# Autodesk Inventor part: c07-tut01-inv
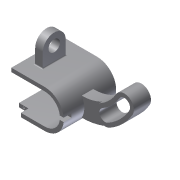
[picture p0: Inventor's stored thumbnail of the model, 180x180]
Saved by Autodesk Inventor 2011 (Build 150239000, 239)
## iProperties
Created: 2010-03
Part Number: c07-tut01-inv
Document SubType Name: Modeling
Designer: CADSoft
Density: 1 g/cm^3
Author: CADSoft
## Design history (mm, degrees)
sketch "Sketch1"
  geometry: 1 further point
sketch "Sketch2"
  geometry: L1 (0, 20)-(35, 20); L2 (35, 20)-(35, 16); L3 (35, 16)-(0, 16); L4 (0, -16)-(35, -16); L5 (35, -16)-(35, -20); L6 (35, -20)-(0, -20); A1 r 20 centre (0, 0) between (0, 20) and (0, -20); A2 r 16 centre (0, 0) between (0, 16) and (0, -16); 1 further point
  constraints: 12 end point, 4 point on circle, 3 equal length, 2 centre point, 1 coincident
  dimensions: "d0" = 20 radius of A1; "d1" = 35 distance of L1.start L1.end; "d2" = 4 distance of L1.end L2.end
extrude "Extrusion1" new body sketch "Sketch2" stored distance "d3" = 55; taper "d4" = 0 deg
sketch "Sketch3"
  geometry: A1 r 45 centre (-17.5, 55) between (-56.409, 32.393) and (-17.32, 10); A2 r 65 centre (-17.5, 55) between (-73.702, 22.345) and (-17.321, -10); A3 r 20 centre (0, 0) between (-17.32, 10) and (-17.321, -10); A4 r 10 centre (-65.055, 27.369) between (-56.409, 32.393) and (-73.702, 22.345); 1 further point
  constraints: 8 point on circle, 4 centre point, 2 coincident, 2 tangent
  dimensions: "d5" = 45 radius of A1; "d6" = 65 radius of A2; "d7" = 17.5 horizontal distance of point (0, 0) A1.centre; "d8" = 55 vertical distance of point (0, 0) A1.centre; "d9" = 60 deg dimension on A1.centre A2.start A2.end; "d10" = 20 radius of A3
extrude "Extrusion2" join sketch "Sketch3" stored distance "d11" = 12; taper "d12" = 0 deg
hole "Hole1" diameter "d52" = 2; stored, may be unused: countersink angle "d56" = 90 deg, drill point angle "d58" = 118 deg; dims "d50" = 5, "d51" = 2, "d53" = 6, "d54" = 4, "d55" = 2, "d57" = 4
body "Solid1"
sketch "Sketch4"
  geometry: A1 r 45 centre (-17.5, 55) between (-56.409, 32.393) and (-39.892, 15.967); A2 r 65 centre (-17.5, 55) between (-73.702, 22.345) and (-49.845, -1.381); A3 r 10 centre (-65.055, 27.369) between (-56.409, 32.393) and (-73.702, 22.345); A4 r 10 centre (-44.868, 7.293) between (-49.845, -1.381) and (-39.892, 15.967); A5 r 10 centre (-65.055, 27.369) between (-56.409, 32.393) and (-73.702, 22.345) reference; A6 r 45 centre (-17.5, 55) between (-56.409, 32.393) and (-17.32, 10) reference; A7 r 65 centre (-17.5, 55) between (-73.702, 22.345) and (-17.321, -10) reference; 1 further point
  constraints: 8 point on circle, 4 centre point, 4 tangent, 3 concentric, 1 coincident
  dimensions: "d30" = 10 radius of A3; "d31" = 30 deg dimension on A1.centre A4.centre A3.centre
extrude "Extrusion3" join sketch "Sketch4" stored distance "d32" = 18; taper "d33" = 0 deg
sketch "Sketch5"
  geometry: A1 r 10 centre (65.055, 27.369) between (73.702, 22.345) and (56.409, 32.393) reference; A2 r 45 centre (17.5, 55) between (39.892, 15.967) and (56.409, 32.393) reference; A3 r 10 centre (44.868, 7.293) between (39.892, 15.967) and (49.845, -1.381) reference; A4 r 65 centre (17.5, 55) between (49.845, -1.381) and (73.702, 22.345) reference; A5 r 6 centre (65.055, 27.369) between (70.243, 24.354) and (59.867, 30.383); A6 r 61 centre (17.5, 55) between (47.854, 2.088) and (70.243, 24.354); A7 r 6 centre (44.868, 7.293) between (41.883, 12.497) and (47.854, 2.088); A8 r 49 centre (17.5, 55) between (41.883, 12.497) and (59.867, 30.383); 1 further point
  constraints: 8 point on circle, 4 centre point, 3 other
  dimensions: "d34" = 6 radius of A5
extrude "Extrusion4" cut sketch "Sketch5" distance "d35" = 18; taper "d36" = 0 deg
workplane "Work Plane1"
sketch "Sketch10"
  geometry: L1 (4, 15.5)-(4, 39.5); L2 (4, 39.5)-(19, 39.5); L3 (19, 15.5)-(4, 15.5); L4 (4, 55)-(4, 0) reference; L5 (-36, 55)-(4, 55) reference; C1 r 6 at (19, 27.5); A1 r 12 centre (19, 27.5) between (19, 15.5) and (19, 39.5); 1 further point
  constraints: 6 end point, 2 centre point, 2 point on circle, 2 point on line, 1 coincident, 1 parallel, 1 perpendicular, 1 tangent
  dimensions: "d38" = 12 radius of A1; "d39" = 27.5 distance from line of L5 A1.centre; "d40" = 15 distance from line of L4 A1.centre; "d41" = 12 diameter of C1
extrude "Extrusion5" join sketch "Sketch10" distance "d42" = 8; taper "d43" = 0 deg
fillet "Fillet1" dims "d44" = 1
sketch "Sketch11"
  geometry: L1 (0, -20)-(-35, -20) reference; L2 (-35, -16)-(-25, -16); L3 (-25, -16)-(-25, -20); L4 (-25, -20)-(-35, -20); L5 (-35, -20)-(-35, -16); L6 (15.875, 2)-(19.9, 2); L7 (15.875, -2)-(19.9, -2); A1 r 20 centre (0, 0) between (0, -20) and (0, 20) reference; A2 r 16 centre (0, 0) between (0, -16) and (0, 16) reference; A3 r 16 centre (0, 0) between (15.875, -2) and (15.875, 2); A4 r 20 centre (0, 0) between (19.9, -2) and (19.9, 2)
  constraints: 12 end point, 8 point on circle, 2 centre point, 1 point on line
  dimensions: "d45" = 10 distance of L2.start L2.end; "d46" = 4 distance between parallel lines of L7 L6; "d47" = 2 distance from line of A1.centre L6
extrude "Extrusion6" cut sketch "Sketch11" distance "d48" = 8; taper "d49" = 0 deg
other parameters: "d37" = -17.5
